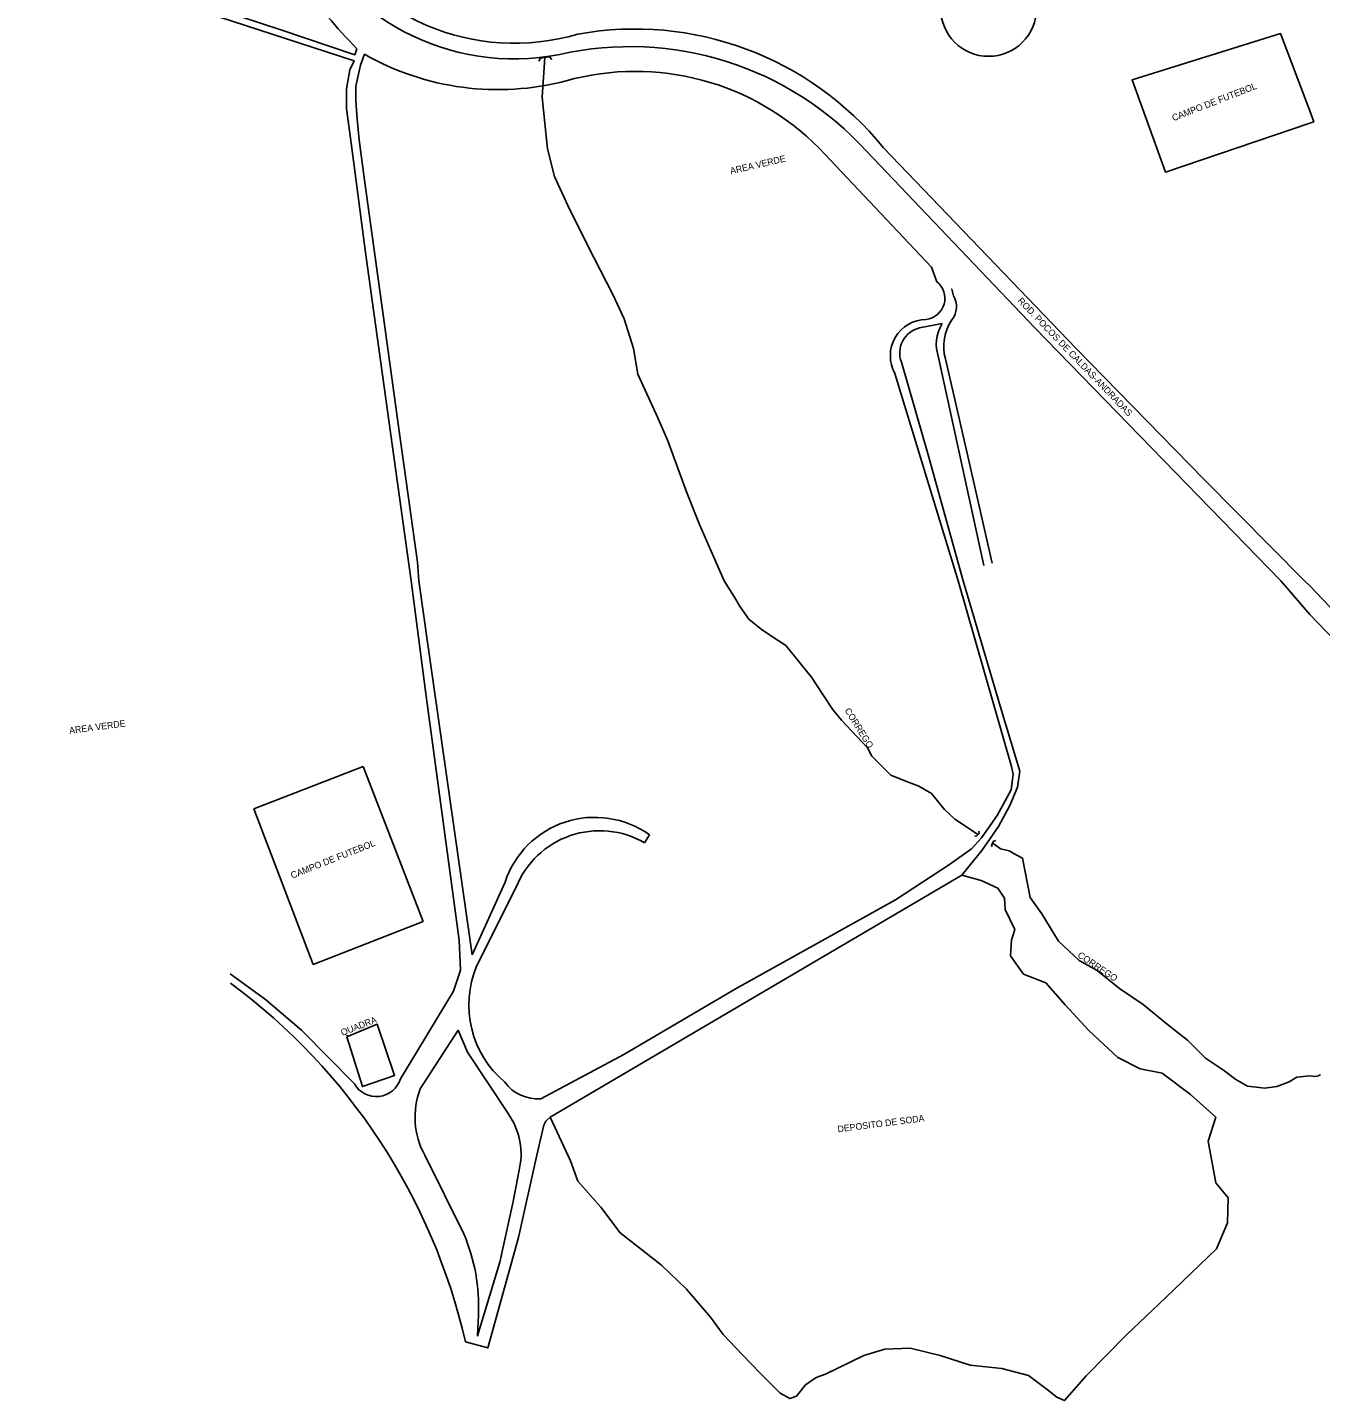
# Model space of a CAD drawing. Extents: x 325899 to 363134, y 7578590 to 7592502.
# Drawn here: x 336102 to 336888, y 7582504 to 7583338 of the extents above; entities that cross this region are included whole.
import ezdxf

# ---------------------------------------------------------------- set-up
doc = ezdxf.new("R2010")
doc.units = 0
for name, color, linetype in [('EDIFEXISTENT', 7, 'Continuous'), ('EDIFFAIXADOM', 7, 'Continuous'), ('EDIFIDENTIF', 7, 'Continuous'), ('EDIFOBRAEXIS', 7, 'Continuous'), ('EDIFOBRAPROJ', 7, 'Continuous')]:
    doc.layers.add(name, color=color, linetype=linetype)

msp = doc.modelspace()

# ---------------------------------------------------------------- linework, layer by layer
at = {"layer": 'EDIFEXISTENT'}
for p, q in [((336412.81, 7583317.55), (336413.87, 7583319.39)), ((336413.87, 7583319.39), (336419.16, 7583320.05)), ((336419.16, 7583320.05), (336420.6, 7583318.56)), ((336239.47, 7582863.28), (336305.89, 7582889.09)), ((336305.89, 7582889.09), (336342.52, 7582794.87)), ((336275.53, 7582768.83), (336239.47, 7582863.28)), ((336677.63, 7582846.6), (336679, 7582846.82)), ((336679, 7582846.82), (336680.36, 7582848.22)), ((336680.36, 7582848.22), (336680.19, 7582849.72)), ((336689.18, 7582843.58), (336690.47, 7582844.08)), ((336688.01, 7582841.01), (336689.18, 7582843.58)), ((336688.35, 7582840.12), (336688.01, 7582841.01)), ((336342.52, 7582794.87), (336275.53, 7582768.83))]:
    msp.add_line(p, q, dxfattribs=at)
at = {"layer": 'EDIFFAIXADOM'}
msp.add_lwpolyline([(336651.52, 7583192.33), (336583.18, 7583264.57)], dxfattribs=at)
for centre, radius, start, end in [((336702.29, 7583705.21), 552.02, 212.5213, 223.54067), ((336387.86, 7583463.47), 163.26, 240.23817, 284.71272), ((336471.43, 7583154.39), 156.93, 44.59548, 105.56474)]:
    msp.add_arc(centre, radius, start, end, dxfattribs=at)
at = {"layer": 'EDIFOBRAEXIS'}
for points in [[(336881.39, 7583287.35), (336863.59, 7583334.22), (336773.38, 7583306.08), (336793.62, 7583250.08), (336881.39, 7583279.93)], [(336525.48, 7583001.91), (336525.48, 7583001.91), (336518.99, 7583016.65), (336518.99, 7583016.65), (336510.48, 7583035.96), (336510.48, 7583035.96), (336502.62, 7583055.92), (336502.62, 7583055.92), (336491.08, 7583086.76), (336485.18, 7583100.9), (336485.18, 7583100.9), (336473.03, 7583127.46), (336470.25, 7583142.95), (336464.61, 7583160.93), (336457.81, 7583175.72), (336457.81, 7583175.72), (336442.62, 7583205.4), (336430.3, 7583229.77), (336422.31, 7583247.35), (336417.98, 7583264.29), (336416.46, 7583279.84), (336416.46, 7583279.84), (336414.83, 7583295.6), (336414.83, 7583295.6), (336416.43, 7583319.71)], [(336881.39, 7583287.35), (336883.74, 7583280.73), (336881.39, 7583279.93)], [(336863.75, 7583001.91), (336714.1, 7583155.69), (336612.18, 7583262.57)], [(336622.26, 7583264.93), (336739.16, 7583143.13), (336817.05, 7583063.55), (336878.09, 7583001.91)], [(336525.48, 7583001.91), (336531.33, 7582992.51), (336535.09, 7582986.07), (336540.46, 7582978.56), (336547.92, 7582972.43), (336553.57, 7582968.67), (336563, 7582962.47), (336578.43, 7582943.36), (336585.42, 7582932.77), (336591.21, 7582923.93), (336596.83, 7582917.09), (336612.51, 7582900.37), (336615.17, 7582895.26), (336620.41, 7582889.96), (336626.78, 7582883.76), (336635.26, 7582880.33), (336643.83, 7582877.04), (336651.35, 7582872.61), (336659.42, 7582862.81), (336665.66, 7582856.94), (336675.09, 7582850.78), (336679.62, 7582847.66)], [(336863.75, 7583001.91), (336881.39, 7582981.34)], [(336878.12, 7583001.91), (336881.39, 7582998.73)], [(337311.54, 7582547.37), (336881.39, 7582998.73)], [(336881.39, 7582981.34), (337280.69, 7582566)], [(336688.71, 7582842.44), (336693.45, 7582838.93), (336698.73, 7582837.78), (336702.56, 7582835.52), (336706.78, 7582833.43), (336711.33, 7582809.36), (336718.59, 7582799.58), (336728.59, 7582782.96), (336741.28, 7582771.22), (336752.05, 7582765.1), (336765.66, 7582754.19), (336780.13, 7582744.4), (336794.95, 7582732.36), (336806.95, 7582722.72), (336818.01, 7582711.84), (336828.91, 7582704.53), (336836.52, 7582698.85), (336843.5, 7582694.75), (336853.99, 7582693.63), (336861.38, 7582694.55), (336868.77, 7582697.51), (336873.58, 7582700.28), (336881.39, 7582701.14)], [(336419.73, 7582675.97), (336431.95, 7582649.42), (336436.49, 7582637.06), (336450.38, 7582621.36), (336462.14, 7582605.76), (336487.25, 7582586.12), (336502.47, 7582571.45), (336517.18, 7582554.47), (336524.71, 7582544.06), (336536.61, 7582531.56), (336547.09, 7582520.66), (336559.52, 7582508.23), (336565.24, 7582505.03), (336569.36, 7582506.41), (336574.76, 7582513.31), (336581.26, 7582517.84), (336586.95, 7582519.84), (336610.34, 7582531.2), (336623.12, 7582535.07), (336638.56, 7582535.68), (336656.8, 7582531.29), (336674.98, 7582525.33), (336694.13, 7582523.32), (336710.4, 7582518.98), (336721.74, 7582510.58), (336727.58, 7582505.85), (336732.34, 7582503.85), (336745.38, 7582518.87), (336770.02, 7582543.81), (336793.92, 7582566.51), (336824.71, 7582596.05), (336831.42, 7582611.8), (336831.86, 7582626.92), (336824.35, 7582636.01), (336819.56, 7582661.43), (336824.27, 7582675.93), (336808.89, 7582689.72), (336791.66, 7582702.73), (336778.21, 7582705.38), (336764.67, 7582712.24), (336747.07, 7582728.66), (336732.65, 7582744.27), (336720.94, 7582757.56), (336707.4, 7582762.92), (336699.39, 7582774.07), (336700, 7582783.42), (336702.05, 7582790.07), (336696.23, 7582802.16), (336695.88, 7582809.13), (336691.71, 7582815.05), (336681.71, 7582819.86), (336669.91, 7582823.09)], [(336296.09, 7582724.81), (336314.57, 7582732.44), (336325.07, 7582701.4), (336305.56, 7582694.62), (336296.09, 7582724.81)], [(336887.96, 7582701.91), (336886.76, 7582701.08), (336884.71, 7582700.75), (336881.39, 7582701.14)]]:
    msp.add_lwpolyline(points, dxfattribs=at)
for centre, radius, start, end in [((336397.69, 7583461.93), 143.06, 202.82404, 281.20152), ((336397.87, 7583464.5), 136.12, 207.51308, 286.45765), ((336470.98, 7583142.31), 194.73, 39.02646, 100.2206), ((336468.2, 7583131.92), 194.42, 42.22013, 102.69257)]:
    msp.add_arc(centre, radius, start, end, dxfattribs=at)
at = {"layer": 'EDIFOBRAPROJ'}
for points in [[(336101.92, 7583388.96), (336157.09, 7583369.08), (336255.91, 7583336.46), (336301.01, 7583321.45), (336302.13, 7583324.93)], [(336335.11, 7583001.91), (336326.95, 7583061.28), (336307.35, 7583201.2), (336300.44, 7583253.92), (336297.48, 7583276.81), (336295.81, 7583288.54), (336295.85, 7583300.74), (336297.82, 7583312.19), (336300.49, 7583317.76), (336102.34, 7583382.22)], [(336339.92, 7583001.91), (336338.95, 7583013.23), (336327.77, 7583092.75), (336318.22, 7583163.31), (336306.88, 7583245.29), (336303.59, 7583269.65), (336302.33, 7583282.17), (336301.51, 7583293.32), (336301.55, 7583302.24), (336304.38, 7583315.02), (336306.82, 7583321.74), (336306.82, 7583321.74)], [(336654.77, 7583183.47), (336651.52, 7583192.33)], [(336663.79, 7583179.06), (336663.79, 7583179.06), (336664.74, 7583175.03)], [(336657.94, 7583158.14), (336644.15, 7583155.47)], [(336683.2, 7583011.08), (336655.78, 7583137.46)], [(336659.89, 7583136.63), (336672.93, 7583080.08), (336688.34, 7583012.52)], [(336667.68, 7583001.91), (336629.25, 7583127.73)], [(336633.15, 7583134.66), (336649.39, 7583078.39), (336670.69, 7583001.91)], [(336335.11, 7583001.91), (336344.35, 7582931.77), (336364.36, 7582783.59), (336365.21, 7582765.24), (336360.96, 7582752.49), (336328.64, 7582699.38)], [(336339.92, 7583001.91), (336345.28, 7582963.14), (336372.2, 7582774.56)], [(336413.98, 7582687.22), (336464.33, 7582714.09), (336532.78, 7582754.06), (336629.46, 7582808.03), (336662.31, 7582829.58), (336675.8, 7582839.05), (336681.85, 7582845.6), (336691.27, 7582859.24), (336699.79, 7582874.91), (336701.03, 7582884.4), (336700.16, 7582889.02), (336667.68, 7583001.91)], [(336694.05, 7582923.1), (336670.69, 7583001.91)], [(336368.13, 7582539.61), (336381.75, 7582535.8), (336400.45, 7582602.97), (336411.51, 7582652.82), (336414.98, 7582667.65), (336415.82, 7582671.08), (336417.09, 7582673.51), (336419.73, 7582675.97), (336669.91, 7582823.09), (336682.13, 7582837.94), (336692.12, 7582852.64), (336699.15, 7582865.43), (336703.76, 7582876.37), (336705.06, 7582886.13), (336694.05, 7582923.1)], [(336479.98, 7582847.58), (336477.07, 7582842.67)], [(336372.2, 7582774.56), (336392.23, 7582818.71)], [(336398.99, 7582815.68), (336374.9, 7582767.73)], [(336300.62, 7582696.21), (336268.59, 7582728.9), (336246.65, 7582747.52), (336225.19, 7582763.04)], [(336363.75, 7582728.88), (336340.66, 7582693.13)], [(336394.12, 7582678.13), (336394.12, 7582678.13), (336369.46, 7582715.52), (336363.75, 7582728.88), (336363.75, 7582728.88)], [(336343.39, 7582652.92), (336367.12, 7582605.15)], [(336376.03, 7582555.78), (336375.54, 7582543.09), (336389.04, 7582587.83), (336397.25, 7582624.77), (336400.57, 7582642.82)]]:
    msp.add_lwpolyline(points, dxfattribs=at)
msp.add_circle((336686.14, 7583349.63), 29.18, dxfattribs=at)
for centre, radius, start, end in [((336646.7, 7583173.44), 12.88, 276.7326, 51.1531), ((336653.69, 7583168.36), 12.91, 321.97618, 31.11092), ((336648.52, 7583138.55), 22.1, 90.81982, 209.3042), ((336647.74, 7583140.26), 15.63, 103.28914, 201.01357), ((336678.32, 7583145.56), 23.96, 148.32449, 199.77185), ((336687.51, 7583144.24), 28.65, 145.65433, 195.41612), ((336446.77, 7582800.71), 57.44, 54.68688, 161.74167), ((336449.72, 7582795.37), 54.64, 59.95688, 158.18422), ((336431.67, 7582744.24), 61.44, 157.5207, 229.88437), ((336002.68, 7582455.73), 374.95, 12.92642, 53.55921), ((336313.94, 7582703.87), 15.37, 209.91869, 342.99028), ((336412, 7582711.78), 24.65, 216.12366, 274.60983), ((336385.66, 7582675.99), 48.15, 159.15224, 208.62475), ((336359.64, 7582653.59), 42.32, 345.25926, 35.45089), ((336264.72, 7582561.18), 111.44, 357.22408, 23.24054)]:
    msp.add_arc(centre, radius, start, end, dxfattribs=at)

# ---------------------------------------------------------------- texts
at = {"layer": 'EDIFIDENTIF'}
for s, rotation, p in [('CAMPO DE FUTEBOL', 21.31396, (336798.56, 7583281)), ('AREA VERDE', 13.02975, (336529.5, 7583248.78)), ('ROD. POCOS DE CALDAS-ANDRADAS', 313.92056, (336703.47, 7583171.61)), ('CORREGO', 302.04155, (336598.39, 7582923.07)), ('AREA VERDE', 7.57252, (336127.55, 7582908.82)), ('CAMPO DE FUTEBOL', 21.65875, (336262.87, 7582820.82)), ('CORREGO', 326.2939, (336739.85, 7582773.48)), ('QUADRA', 21.42564, (336293.32, 7582725.32)), ('DEPOSITO DE SODA', 7.26867, (336594.57, 7582666.75))]:
    msp.add_text(s, height=4, rotation=rotation, dxfattribs=at).set_placement(p)

doc.saveas('drawing.dxf')
